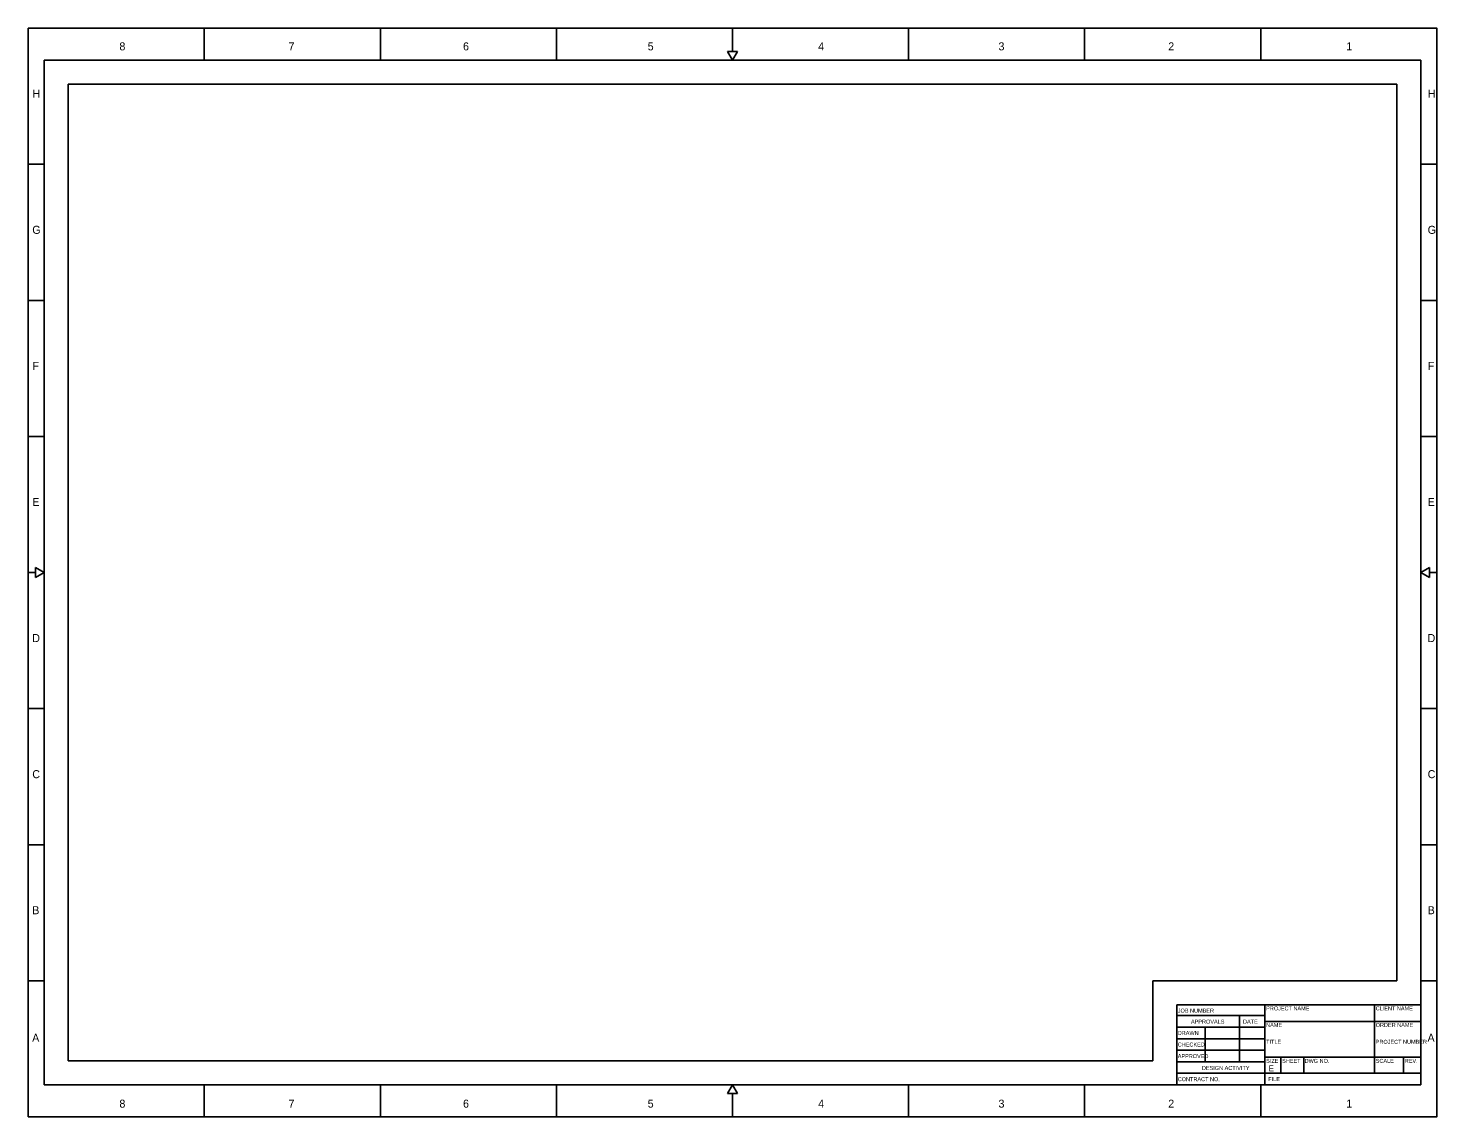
# Model space of a CAD drawing. Extents: x 0 to 176, y 0 to 136.
import ezdxf

# ---------------------------------------------------------------- set-up
doc = ezdxf.new("R2010")
doc.units = 0
for name, color, linetype in [('Border', 7, 'Continuous'), ('BorderPlot', 7, 'Continuous'), ('ClipShape', 7, 'Continuous'), ('TitleBlock', 7, 'Continuous'), ('TitleBlockText', 7, 'Continuous')]:
    doc.layers.add(name, color=color, linetype=linetype)

# ---------------------------------------------------------------- blocks, each defined once
blk = doc.blocks.new('DC-ANSI-E_SC48')
at = {"layer": 'Border'}
for p, q in [((0.4583, 2.8333), (0.4583, 2.75)), ((0.9167, 2.8333), (0.9167, 2.75)), ((1.375, 2.8333), (1.375, 2.75)), ((1.8333, 2.7726), (1.8333, 2.8333)), ((2.2917, 2.8333), (2.2917, 2.75)), ((2.75, 2.8333), (2.75, 2.75)), ((3.2083, 2.8333), (3.2083, 2.75)), ((1.8333, 2.75), (1.8203, 2.7726)), ((1.8203, 2.7726), (1.8464, 2.7726)), ((1.8333, 2.75), (1.8464, 2.7726)), ((0.0417, 2.4792), (0, 2.4792)), ((3.625, 2.4792), (3.6667, 2.4792)), ((0.0417, 2.125), (0, 2.125)), ((3.625, 2.125), (3.6667, 2.125)), ((0.0417, 1.7708), (0, 1.7708)), ((3.625, 1.7708), (3.6667, 1.7708)), ((0.0191, 1.4167), (0, 1.4167)), ((0.0417, 1.4167), (0.0191, 1.4297)), ((0.0191, 1.4297), (0.0191, 1.4036)), ((0.0191, 1.4036), (0.0417, 1.4167)), ((3.625, 1.4167), (3.6476, 1.4297)), ((3.6476, 1.4036), (3.625, 1.4167)), ((3.6476, 1.4297), (3.6476, 1.4036)), ((3.6476, 1.4167), (3.6667, 1.4167)), ((0.0417, 1.0625), (0, 1.0625)), ((3.625, 1.0625), (3.6667, 1.0625)), ((0.0417, 0.7083), (0, 0.7083)), ((3.625, 0.7083), (3.6667, 0.7083)), ((0.0417, 0.3542), (0, 0.3542)), ((3.625, 0.3542), (3.6667, 0.3542)), ((0.4583, 0), (0.4583, 0.0833)), ((0.9167, 0), (0.9167, 0.0833)), ((1.375, 0), (1.375, 0.0833)), ((1.8333, 0.0833), (1.8203, 0.0607)), ((1.8333, 0.0833), (1.8464, 0.0607)), ((2.2917, 0), (2.2917, 0.0833)), ((2.75, 0), (2.75, 0.0833)), ((3.2083, 0), (3.2083, 0.0833)), ((1.8203, 0.0607), (1.8464, 0.0607)), ((1.8333, 0.0607), (1.8333, 0))]:
    blk.add_line(p, q, dxfattribs=at)
blk.add_lwpolyline([(3.625, 0.0833), (0.0417, 0.0833), (0.0417, 2.75), (3.625, 2.75)], close=True, dxfattribs=at)
at = {"layer": 'BorderPlot'}
blk.add_lwpolyline([(0, 2.8333), (3.6667, 2.8333), (3.6667, 0), (0, 0)], close=True, dxfattribs=at)
at = {"layer": 'ClipShape'}
for p, q in [((0.1042, 0.1458), (0.1042, 2.6875)), ((0.1042, 2.6875), (3.5625, 2.6875)), ((3.5625, 2.6875), (3.5625, 0.3542)), ((3.5625, 0.3542), (2.9275, 0.3542)), ((2.9275, 0.3542), (2.9275, 0.1458)), ((2.9275, 0.1458), (0.1042, 0.1458))]:
    blk.add_line(p, q, dxfattribs=at)
at = {"layer": 'TitleBlock'}
for p, q in [((2.99, 0.0833), (2.99, 0.2917)), ((2.99, 0.2917), (3.625, 0.2917)), ((2.99, 0.2633), (3.2192, 0.2633)), ((3.1532, 0.1433), (3.1532, 0.2633)), ((3.2192, 0.0833), (3.2192, 0.2917)), ((3.5043, 0.1133), (3.5043, 0.2917)), ((2.99, 0.2333), (3.2192, 0.2333)), ((3.0633, 0.1433), (3.0633, 0.2333)), ((3.2192, 0.2483), (3.625, 0.2483)), ((2.99, 0.2033), (3.2192, 0.2033)), ((2.99, 0.1733), (3.2192, 0.1733)), ((3.2192, 0.155), (3.625, 0.155)), ((3.2608, 0.1133), (3.2608, 0.155)), ((3.3201, 0.1133), (3.3201, 0.155)), ((3.5799, 0.1133), (3.5799, 0.155)), ((2.99, 0.1433), (3.2192, 0.1433)), ((2.99, 0.1133), (3.625, 0.1133)), ((3.625, 0.0833), (3.625, 0.0833))]:
    blk.add_line(p, q, dxfattribs=at)
at = {"layer": 'Border'}
for s, p in [('8', (0.2375, 2.7756)), ('7', (0.6777, 2.7756)), ('6', (1.1319, 2.7756)), ('5', (1.6126, 2.7756)), ('4', (2.0564, 2.7756)), ('3', (2.5257, 2.7756)), ('2', (2.9675, 2.7756)), ('1', (3.431, 2.7756)), ('H', (0.0112, 2.6523)), ('H', (3.6433, 2.6523)), ('G', (0.0107, 2.2981)), ('G', (3.6428, 2.2981)), ('F', (0.0112, 1.9439)), ('F', (3.6433, 1.9439)), ('E', (0.0108, 1.5898)), ('E', (3.6428, 1.5898)), ('D', (0.0107, 1.2356)), ('D', (3.6427, 1.2356)), ('C', (0.0107, 0.8814)), ('C', (3.6428, 0.8814)), ('B', (0.0107, 0.5273)), ('B', (3.6428, 0.5273)), ('A', (0.0104, 0.1954)), ('A', (3.6424, 0.1954)), ('8', (0.2375, 0.0239)), ('7', (0.6777, 0.0239)), ('6', (1.1319, 0.0239)), ('5', (1.6126, 0.0239)), ('4', (2.0564, 0.0239)), ('3', (2.5257, 0.0239)), ('2', (2.9675, 0.0239)), ('1', (3.431, 0.0239))]:
    blk.add_text(s, height=0.0208, dxfattribs=at).set_placement(p)
at = {"layer": 'TitleBlock'}
blk.add_text('E', height=0.0156, dxfattribs=at).set_placement((3.2287, 0.1183))
at = {"layer": 'TitleBlockText'}
for s, height, p in [('JOB NUMBER', 0.01042, (2.9923, 0.2712)), ('PROJECT NAME', 0.010417, (3.2223, 0.2771)), ('CLIENT NAME', 0.010417, (3.5076, 0.2771)), ('DRAWN', 0.01042, (2.9923, 0.2131)), ('APPROVALS', 0.01042, (3.0267, 0.2425)), ('DATE', 0.01042, (3.1622, 0.2425)), ('NAME', 0.01042, (3.2223, 0.2338)), ('ORDER NAME', 0.01042, (3.5076, 0.2338)), ('CHECKED', 0.01042, (2.9923, 0.1829)), ('TITLE', 0.01042, (3.2223, 0.19)), ('PROJECT NUMBER', 0.010417, (3.5076, 0.19)), ('APPROVED', 0.01042, (2.9923, 0.1528)), ('SIZE', 0.01042, (3.2223, 0.1404)), ('SHEET', 0.01042, (3.264, 0.1404)), ('DWG NO.', 0.01042, (3.3224, 0.1404)), ('SCALE', 0.01042, (3.5076, 0.1404)), ('REV.', 0.01042, (3.5832, 0.1404)), ('DESIGN ACTIVITY', 0.010417, (3.0552, 0.122)), ('CONTRACT NO.', 0.010417, (2.9923, 0.0928)), ('FILE', 0.01042, (3.2278, 0.093))]:
    blk.add_text(s, height=height, dxfattribs=at).set_placement(p)

msp = doc.modelspace()

# ---------------------------------------------------------------- block references
at = {"xscale": 48, "yscale": 48}
msp.add_blockref('DC-ANSI-E_SC48', (0, 0), dxfattribs=at)

doc.saveas('drawing.dxf')
